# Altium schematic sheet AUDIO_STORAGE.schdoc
size 127 x 101 mm
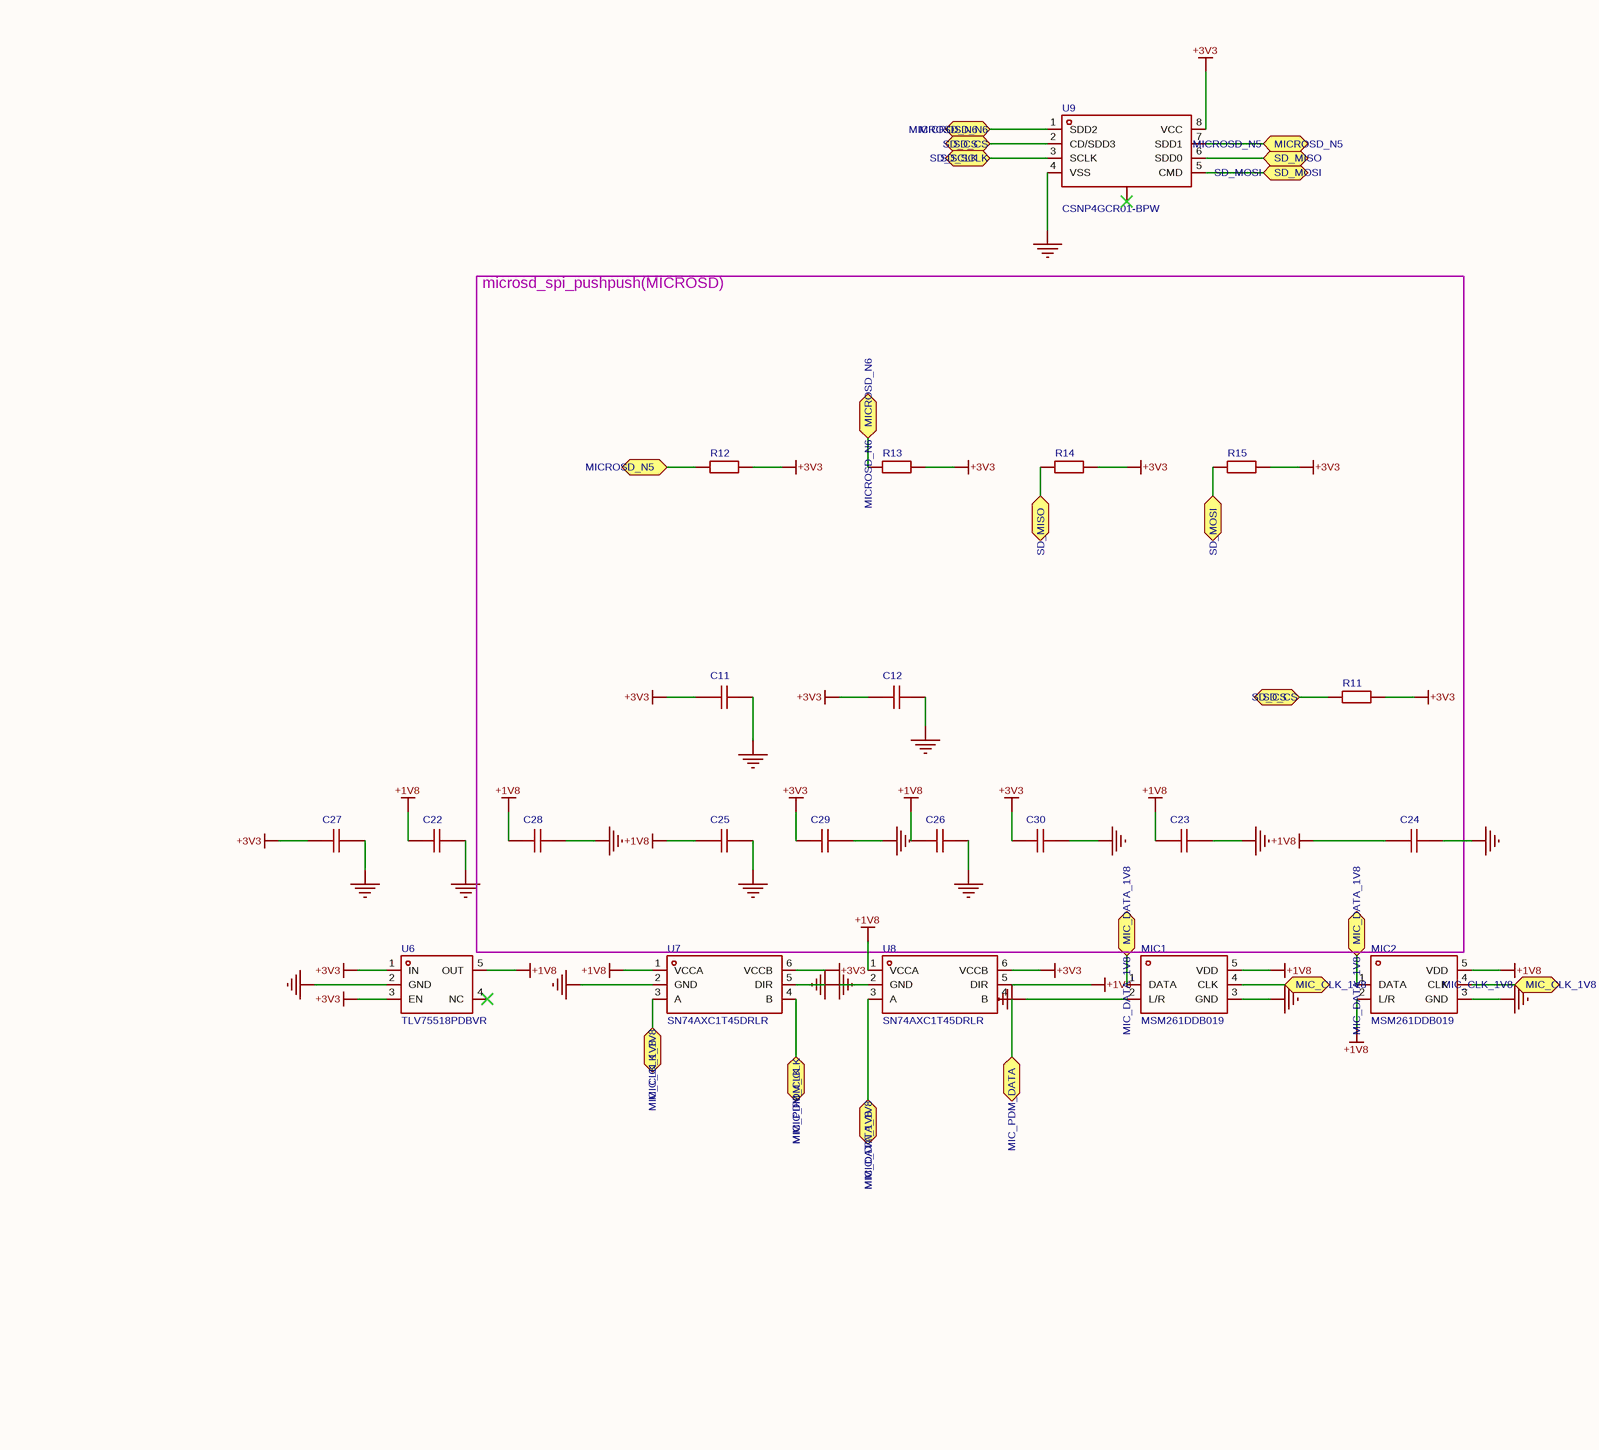
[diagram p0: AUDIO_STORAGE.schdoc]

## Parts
C11  (no value)  [C0805]
C12  (no value)  [C0402]
C22  (no value)  [C0402]
C23  (no value)  [C0402]
C24  (no value)  [C0402]
C25  (no value)  [C0402]
C26  (no value)  [C0402]
C27  (no value)  [C0402]
C28  (no value)  [C0402]
C29  (no value)  [C0402]
C30  (no value)  [C0402]
MIC1  MSM261DDB019  [RHLGA-5L_L3.5-W2.7-P0.82-MSM261DDB019]
MIC2  MSM261DDB019  [RHLGA-5L_L3.5-W2.7-P0.82-MSM261DDB019]
R11  (no value)  [R0402]
R12  (no value)  [R0402]
R13  (no value)  [R0402]
R14  (no value)  [R0402]
R15  (no value)  [R0402]
U6  TLV75518PDBVR  [SOT-23-5_L2.9-W1.6-P0.95-LS2.8-BR]
U7  SN74AXC1T45DRLR  [SOT-563_L1.6-W1.2-P0.50-LS1.6-BL]
U8  SN74AXC1T45DRLR  [SOT-563_L1.6-W1.2-P0.50-LS1.6-BL]
U9  CSNP4GCR01-BPW  [LGA-8_L8.0-W6.0-P1.27]

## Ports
MIC_CLK_1V8 (bidir), MIC_DATA_1V8 (bidir), MIC_PDM_CLK (bidir), MIC_PDM_DATA (bidir), MICROSD_N5 (bidir), MICROSD_N6 (bidir), SD_CS (bidir), SD_MISO (bidir), SD_MOSI (bidir), SD_SCLK (bidir)

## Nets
+1V8: C22.1 C23.1 C24.1 C25.1 C26.1 C28.1 MIC1.5(VDD) MIC2.2(L/R) MIC2.5(VDD) U6.5(OUT) U7.1(VCCA) U8.1(VCCA) U8.5(DIR)
+3V3: C11.1 C12.1 C27.1 C29.1 C30.1 R11.2 R12.2 R13.2 R14.2 R15.2 U6.1(IN) U6.3(EN) U7.6(VCCB) U8.6(VCCB) U9.8(VCC)
GND: C11.2 C12.2 C22.2 C23.2 C24.2 C25.2 C26.2 C27.2 C28.2 C29.2 C30.2 MIC1.2(L/R) MIC1.3(GND) MIC2.3(GND) U6.2(GND) U7.2(GND) U7.5(DIR) U8.2(GND) U9.4(VSS)
MIC_CLK_1V8: MIC1.4(CLK) MIC2.4(CLK) U7.3(A) ; port MIC_CLK_1V8
MIC_DATA_1V8: MIC1.1(DATA) MIC2.1(DATA) U8.3(A) ; port MIC_DATA_1V8
MIC_PDM_CLK: U7.4(B) ; port MIC_PDM_CLK
MIC_PDM_DATA: U8.4(B) ; port MIC_PDM_DATA
MICROSD_N5: R12.1 U9.7(SDD1) ; port MICROSD_N5
MICROSD_N6: R13.1 U9.1(SDD2) ; port MICROSD_N6
SD_CS: R11.1 U9.2(CD/SDD3) ; port SD_CS
SD_MISO: R14.1 U9.6(SDD0) ; port SD_MISO
SD_MOSI: R15.1 U9.5(CMD) ; port SD_MOSI
SD_SCLK: U9.3(SCLK) ; port SD_SCLK

Not connected (* = marked no-connect by the designer): U6 4(NC)*; U9 9(NC)*

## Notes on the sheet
- microsd_spi_pushpush(MICROSD)

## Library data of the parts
C11 = GRM21BR61H106KE43L: Manufacturer: muRata(村田); Add into BOM: yes; ModelId: 1ba041120af144c991958decab20d2410819f05c4eef4c71ace90d822a990e87; ModelName: C0805_L2.0-W1.3-H1.3; ModelTransform: 78.74,51.181,0,0,0,0,0,0.0005,0
C12 C22-C26 C29 C30 = CL05B104KO5NNNC: Manufacturer: SAMSUNG(三星); Add into BOM: yes; ModelId: 36a51122f27c49738f86b3bfa98863e00819f05c4eef4c71ace90d822a990e87; ModelName: C0402_L1.0-W0.5-H0.5; ModelTransform: 39.37,19.685,0,0,0,0,0,0,0
C27 C28 = CL05A105KA5NQNC: Manufacturer: SAMSUNG(三星); Add into BOM: yes; ModelId: 36a51122f27c49738f86b3bfa98863e00819f05c4eef4c71ace90d822a990e87; ModelName: C0402_L1.0-W0.5-H0.5; ModelTransform: 39.37,19.685,0,0,0,0,0,0,0
MIC1 MIC2 = MSM261DDB019: Manufacturer: MEMS(敏芯微); Add into BOM: yes
R11-R15 = 0402WGF1002TCE: Manufacturer: UNI-ROYAL(厚声); Add into BOM: yes; ModelId: 98c88bc2b9094f218f3a3e30a70127380819f05c4eef4c71ace90d822a990e87; ModelName: R0402_L1.0-W0.5-H0.4; ModelTransform: 39.37,19.685,0,0,0,0,0,0,0
U6 = TLV75518PDBVR: Manufacturer: TI(德州仪器); Add into BOM: yes; 3D Model: 7ba65df16e7b4570af156e925f9c37fe0819f05c4eef4c71ace90d822a990e87; 3D Model Transform: 114.173,114.173,0,90,0,0,0,0,0
U7 U8 = SN74AXC1T45DRLR: Manufacturer: TI(德州仪器); Add into BOM: yes; 3D Model: ae4c13e967cf4f598e77975e9d61b1bf0819f05c4eef4c71ace90d822a990e87; 3D Model Transform: 62.992,62.992,0,90,0,0,-0.005,0.005,0; ModelName: SOT-563-6P_L1.6-W1.2-H0.6-LS1.6-P0.50
U9 = CSNP4GCR01-BPW: Manufacturer: CS(创世); Add into BOM: yes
